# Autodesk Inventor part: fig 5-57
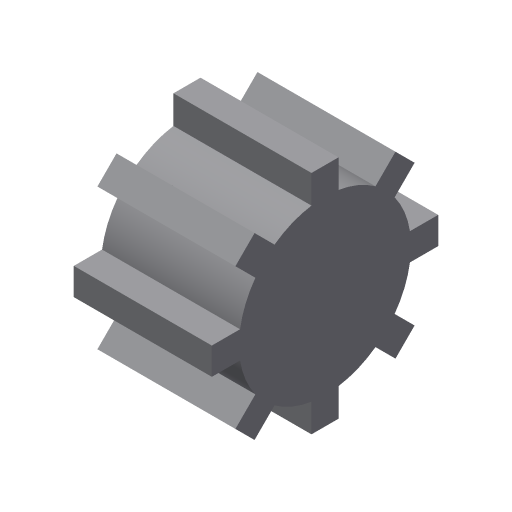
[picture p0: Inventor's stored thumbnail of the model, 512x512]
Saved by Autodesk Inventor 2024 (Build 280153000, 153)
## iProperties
Created: 2005-12
Part Number: fig 5-57
Document SubType Name: Modeling
Designer: CADCIM
Density: 1 g/cm^3
Material: Generic
Appearance: Default
Author: CADCIM
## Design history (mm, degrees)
sketch "Sketch1"
  geometry: C1 r 27.506 at (0, 0)
  constraints: 1 centre point
extrude "Extrusion1" new body sketch "Sketch1" distance "d0" = 20; taper "d1" = 0 deg
sketch "Sketch2"
  geometry: L1 (-12.302, -1.705)-(-16.396, -1.705); L2 (-16.396, -1.705)-(-16.396, 2.216); L3 (-16.396, 2.216)-(-12.302, 2.216); L4 (-7.311, -9.833)-(-10.206, -12.728); L5 (-10.206, -12.728)-(-12.979, -9.955); L6 (-12.979, -9.955)-(-10.084, -7.06); L7 (1.966, -12.051)-(1.966, -16.145); L8 (1.966, -16.145)-(-1.956, -16.145); L9 (-1.956, -16.145)-(-1.956, -12.051); L10 (10.093, -7.06)-(12.988, -9.955); L11 (12.988, -9.955)-(10.215, -12.728); L12 (10.215, -12.728)-(7.32, -9.833); L13 (12.311, 2.216)-(16.405, 2.216); L14 (16.405, 2.216)-(16.405, -1.705); L15 (16.405, -1.705)-(12.311, -1.705); L16 (7.32, 10.344)-(10.215, 13.239); L17 (10.215, 13.239)-(12.988, 10.466); L18 (12.988, 10.466)-(10.093, 7.571); L19 (-1.956, 12.562)-(-1.956, 16.656); L20 (-1.956, 16.656)-(1.966, 16.656); L21 (1.966, 16.656)-(1.966, 12.562); L22 (-10.084, 7.571)-(-12.979, 10.466); L23 (-12.979, 10.466)-(-10.206, 13.239); L24 (-10.206, 13.239)-(-7.311, 10.344); A1 r 12.462 centre (0.005, 0.256) between (-12.302, -1.705) and (-10.084, -7.06); A2 r 12.462 centre (0.005, 0.256) between (-7.311, -9.833) and (-1.956, -12.051); A3 r 12.462 centre (0.005, 0.256) between (1.966, -12.051) and (7.32, -9.833); A4 r 12.462 centre (0.005, 0.256) between (10.093, -7.06) and (12.311, -1.705); A5 r 12.462 centre (0.005, 0.256) between (12.311, 2.216) and (10.093, 7.571); A6 r 12.462 centre (0.005, 0.256) between (7.32, 10.344) and (1.966, 12.562); A7 r 12.462 centre (0.005, 0.256) between (-1.956, 12.562) and (-7.311, 10.344); A8 r 12.462 centre (0.005, 0.256) between (-10.084, 7.571) and (-12.302, 2.216)
  constraints: 48 end point, 16 point on circle, 8 centre point, 2 parallel, 1 horizontal, 1 perpendicular, 57 other
  dimensions: "d4" = 360 deg dimension on A1.centre L2.end (derived)
extrude "Extrusion2" sketch "Sketch2" distance "d6" = 20; taper "d7" = 0 deg
body "Solid1"
